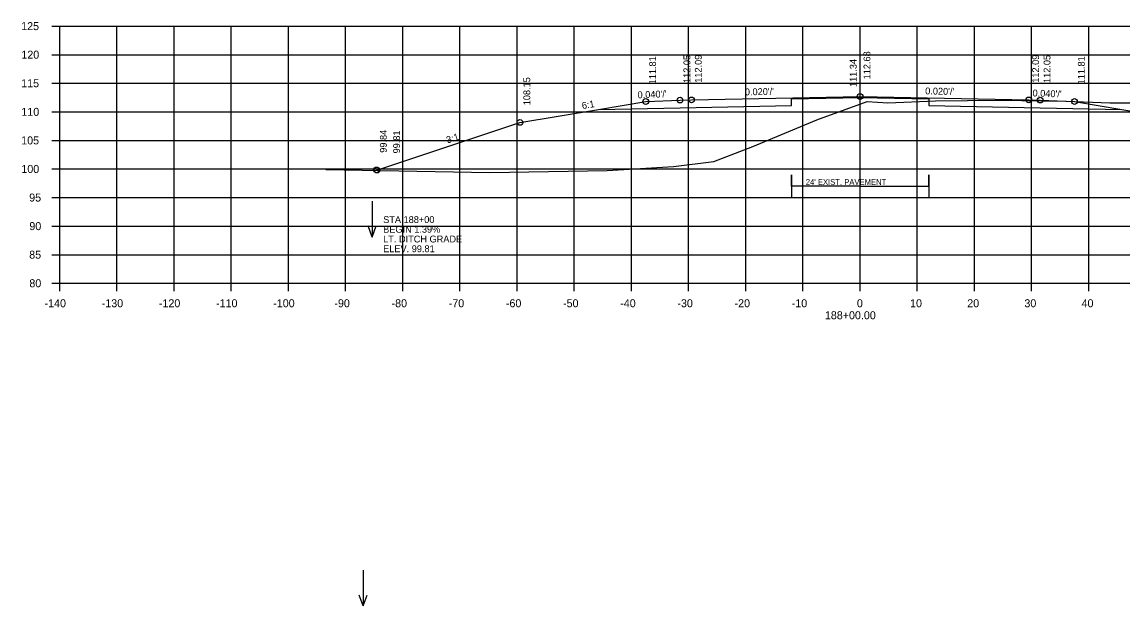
# Model space of a CAD drawing. Extents: x 1175611 to 1176402, y -433344 to -416213.
# Drawn here: x 1175982.1 to 1176174.7, y -426338.8 to -426236.5 of the extents above; entities that cross this region are included whole.
import ezdxf

# ---------------------------------------------------------------- set-up
doc = ezdxf.new("R2010")
doc.units = 0
doc.layers.add('R_No Plot', color=7, linetype='Continuous')

msp = doc.modelspace()

# ---------------------------------------------------------------- linework, layer by layer
at = {"layer": 'R_No Plot'}
for p, q in [((1175987.29, -426237.27), (1175988.69, -426237.27)), ((1175988.69, -426237.27), (1176268.69, -426237.27)), ((1175988.69, -426282.27), (1175988.69, -426237.27)), ((1175988.69, -426282.27), (1175988.69, -426237.27)), ((1175998.69, -426282.27), (1175998.69, -426237.27)), ((1176008.69, -426282.27), (1176008.69, -426237.27)), ((1176018.69, -426282.27), (1176018.69, -426237.27)), ((1176028.69, -426282.27), (1176028.69, -426237.27)), ((1176038.69, -426282.27), (1176038.69, -426237.27)), ((1176048.69, -426282.27), (1176048.69, -426237.27)), ((1176058.69, -426282.27), (1176058.69, -426237.27)), ((1176068.69, -426282.27), (1176068.69, -426237.27)), ((1176078.69, -426282.27), (1176078.69, -426237.27)), ((1176088.69, -426282.27), (1176088.69, -426237.27)), ((1176098.69, -426282.27), (1176098.69, -426237.27)), ((1176108.69, -426282.27), (1176108.69, -426237.27)), ((1176118.69, -426282.27), (1176118.69, -426237.27)), ((1176128.69, -426282.27), (1176128.69, -426237.27)), ((1176138.69, -426282.27), (1176138.69, -426237.27)), ((1176148.69, -426282.27), (1176148.69, -426237.27)), ((1176158.69, -426282.27), (1176158.69, -426237.27)), ((1176168.69, -426282.27), (1176168.69, -426237.27)), ((1175987.29, -426242.27), (1175988.69, -426242.27)), ((1175988.69, -426242.27), (1176268.69, -426242.27)), ((1175987.29, -426247.27), (1175988.69, -426247.27)), ((1175988.69, -426247.27), (1176268.69, -426247.27)), ((1175987.29, -426252.27), (1175988.69, -426252.27)), ((1175988.69, -426252.27), (1176268.69, -426252.27)), ((1175987.29, -426257.27), (1175988.69, -426257.27)), ((1175988.69, -426257.27), (1176268.69, -426257.27)), ((1175987.29, -426262.27), (1175988.69, -426262.27)), ((1175988.69, -426262.27), (1176268.69, -426262.27)), ((1176128.69, -426265.27), (1176116.69, -426265.27)), ((1176128.69, -426265.27), (1176140.69, -426265.27)), ((1175987.29, -426267.27), (1175988.69, -426267.27)), ((1175988.69, -426267.27), (1176268.69, -426267.27)), ((1176043.35, -426267.89), (1176043.35, -426274.18)), ((1175987.29, -426272.27), (1175988.69, -426272.27)), ((1175988.69, -426272.27), (1176268.69, -426272.27)), ((1176043.35, -426274.18), (1176042.65, -426272.25)), ((1176043.35, -426274.18), (1176044.05, -426272.25)), ((1175987.29, -426277.27), (1175988.69, -426277.27)), ((1175988.69, -426277.27), (1176268.69, -426277.27)), ((1175987.29, -426282.27), (1175988.69, -426282.27)), ((1175988.69, -426282.27), (1176268.69, -426282.27)), ((1175988.69, -426282.27), (1176268.69, -426282.27)), ((1175988.69, -426283.67), (1175988.69, -426282.27)), ((1175998.69, -426283.67), (1175998.69, -426282.27)), ((1176008.69, -426283.67), (1176008.69, -426282.27)), ((1176018.69, -426283.67), (1176018.69, -426282.27)), ((1176028.69, -426283.67), (1176028.69, -426282.27)), ((1176038.69, -426283.67), (1176038.69, -426282.27)), ((1176048.69, -426283.67), (1176048.69, -426282.27)), ((1176058.69, -426283.67), (1176058.69, -426282.27)), ((1176068.69, -426283.67), (1176068.69, -426282.27)), ((1176078.69, -426283.67), (1176078.69, -426282.27)), ((1176088.69, -426283.67), (1176088.69, -426282.27)), ((1176098.69, -426283.67), (1176098.69, -426282.27)), ((1176108.69, -426283.67), (1176108.69, -426282.27)), ((1176118.69, -426283.67), (1176118.69, -426282.27)), ((1176128.69, -426283.67), (1176128.69, -426282.27)), ((1176138.69, -426283.67), (1176138.69, -426282.27)), ((1176148.69, -426283.67), (1176148.69, -426282.27)), ((1176158.69, -426283.67), (1176158.69, -426282.27)), ((1176168.69, -426283.67), (1176168.69, -426282.27)), ((1176041.78, -426332.47), (1176041.78, -426338.75)), ((1176041.78, -426338.75), (1176041.08, -426336.83)), ((1176041.78, -426338.75), (1176042.48, -426336.83))]:
    msp.add_line(p, q, dxfattribs=at)
for points in [[(1176043.97, -426262.53), (1176069.19, -426254.12), (1176082.92, -426251.84), (1176091.19, -426250.46), (1176097.19, -426250.22), (1176099.19, -426250.18), (1176128.69, -426249.59), (1176158.19, -426250.18), (1176160.19, -426250.22), (1176166.19, -426250.46), (1176174.46, -426251.84), (1176188.19, -426254.12), (1176209.69, -426261.29), (1176210.13, -426261.15)], [(1176082.92, -426251.84), (1176097.19, -426251.55), (1176116.69, -426251.16), (1176116.69, -426249.99), (1176128.69, -426249.75), (1176140.69, -426249.99), (1176140.69, -426251.16), (1176160.19, -426251.55), (1176174.46, -426251.84)], [(1176035.22, -426262.38), (1176063.92, -426262.88), (1176084.43, -426262.52), (1176096.07, -426261.83), (1176103.1, -426260.98), (1176109.94, -426258.32), (1176121.14, -426253.65), (1176129.95, -426250.48), (1176133.55, -426250.68), (1176141.9, -426250.35), (1176153.09, -426250.25), (1176164.74, -426250.41), (1176172.37, -426250.67), (1176176.66, -426250.7), (1176186.62, -426254.14), (1176195.21, -426257.51), (1176204.84, -426260.31), (1176216.53, -426262.2), (1176231.05, -426264.07), (1176263.62, -426262.9), (1176268.69, -426261.63)], [(1176116.69, -426265.27), (1176116.69, -426263.27), (1176116.69, -426267.27)], [(1176140.69, -426265.27), (1176140.69, -426263.27), (1176140.69, -426267.27)]]:
    msp.add_lwpolyline(points, dxfattribs=at)
for centre in [(1176091.19, -426250.46), (1176097.19, -426250.22), (1176099.19, -426250.18), (1176128.69, -426249.59), (1176158.19, -426250.18), (1176160.19, -426250.22), (1176166.19, -426250.46), (1176069.19, -426254.12), (1176044.09, -426262.43), (1176044.18, -426262.46)]:
    msp.add_circle(centre, 0.5, dxfattribs=at)

# ---------------------------------------------------------------- texts
for s, height, p in [('125', 1.4, (1175981.94, -426237.97)), ('120', 1.4, (1175981.97, -426242.97)), ('115', 1.4, (1175981.94, -426247.97)), ('110', 1.4, (1175981.97, -426252.97)), ('105', 1.4, (1175981.94, -426257.97)), ('100', 1.4, (1175981.97, -426262.97)), ("24' EXIST. PAVEMENT", 1, (1176119.19, -426265.05)), ('95', 1.4, (1175983.34, -426267.97)), ('STA 188+00', 1.2, (1176045.26, -426271.73)), ('90', 1.4, (1175983.37, -426272.97)), ('BEGIN 1.39%', 1.2, (1176045.26, -426273.43)), ('LT. DITCH GRADE', 1.2, (1176045.26, -426275.13)), ('85', 1.4, (1175983.34, -426277.97)), ('ELEV. 99.81', 1.2, (1176045.26, -426276.83)), ('80', 1.4, (1175983.37, -426282.97)), ('-140', 1.4, (1175986.03, -426286.47)), ('-130', 1.4, (1175996.03, -426286.47)), ('-120', 1.4, (1176006.03, -426286.47)), ('-110', 1.4, (1176016.03, -426286.47)), ('-100', 1.4, (1176026.03, -426286.47)), ('-90', 1.4, (1176036.73, -426286.47)), ('-80', 1.4, (1176046.73, -426286.47)), ('-70', 1.4, (1176056.73, -426286.47)), ('-60', 1.4, (1176066.73, -426286.47)), ('-50', 1.4, (1176076.73, -426286.47)), ('-40', 1.4, (1176086.73, -426286.47)), ('-30', 1.4, (1176096.73, -426286.47)), ('-20', 1.4, (1176106.73, -426286.47)), ('-10', 1.4, (1176116.73, -426286.47)), ('0', 1.4, (1176128.13, -426286.47)), ('10', 1.4, (1176137.43, -426286.47)), ('20', 1.4, (1176147.43, -426286.47)), ('30', 1.4, (1176157.43, -426286.47)), ('40', 1.4, (1176167.43, -426286.47)), ('188+00.00', 1.4, (1176122.53, -426288.57))]:
    msp.add_text(s, height=height, dxfattribs=at).set_placement(p)
for s, rotation, p in [('112.05', 90, (1176098.99, -426247.22)), ('112.09', 90, (1176100.99, -426247.18)), ('112.68', 90, (1176130.49, -426246.59)), ('112.09', 90, (1176159.99, -426247.18)), ('112.05', 90, (1176161.99, -426247.22)), ('111.81', 90, (1176092.99, -426247.46)), ('111.34', 90, (1176128.09, -426247.93)), ('111.81', 90, (1176167.99, -426247.46)), ('108.15', 90, (1176070.99, -426251.12)), ("0.020'/'", 1.1458, (1176108.55, -426249.39)), ("0.020'/'", 358.8542, (1176140.07, -426249.21)), ("0.040'/'", 2.2906, (1176089.79, -426249.91)), ("0.040'/'", 357.7094, (1176158.84, -426249.56)), ('6:1', 9.4623, (1176080.11, -426251.8)), ('99.84', 90, (1176045.89, -426259.43)), ('99.81', 90, (1176048.21, -426259.55)), ('3:1', 18.4349, (1176056.53, -426257.82))]:
    msp.add_text(s, height=1.2, rotation=rotation, dxfattribs=at).set_placement(p)

doc.saveas('drawing.dxf')
